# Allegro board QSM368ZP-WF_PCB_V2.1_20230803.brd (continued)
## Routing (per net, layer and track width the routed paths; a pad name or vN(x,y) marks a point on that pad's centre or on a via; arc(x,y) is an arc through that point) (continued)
GND_FIELD SIGNAL: length 54.9
  TOP w0.5: J0901.15 116.65,9.92 116.65,15.43 114.78,17.3 D0901.2 113.84,18.19 R0946.1 113.88,19.62 113.42,20.07 C0920.1 C0909.1 ; v1(103.62,12.22) 106.09,14.69 D0903.2 107.53,17.43 C0901.1
  INNER LAYER 3 w0.5: J0901.15 116.75,8.68 116.75,4.28 115.25,2.77 108.35,2.77 101.78,9.35 J0901.16 102.69,12.22 v1(103.62,12.22)
VBATT: length 144.6
  TOP w0.1: v1(25.38,83.1) 26.85,81.62 v1(28.18,81.62)
  TOP w0.25: R0515.2 12.12,92.03 11.88,92.28 11.88,92.3 9.9,94.28 9.9,97.75 11.15,99 13.4,99 14.3,98.1 C0530.1
  TOP w0.3: C0530.1 R0504.2 U0502.1 ; v1(81.28,68.03) 83.08,69.83 84.33,69.83 90.62,76.12 90.62,83.85 89.67,84.8 89.67,85.65 v1(89.58,85.75)
  TOP w0.5: R0515.2 13.53,90.05 13.17,89.7 13.17,85.97 13.67,85.47 R0120.2
  TOP w1: R0120.2 18.3,85.47
  TOP w1.82: J0102.1 22,83.38 19.9,85.47 18.3,85.47
  TOP w1.9: 74.7,85.03 73.27,83.59 69.26,83.59
  TOP w3: 60.3,79.35 63.73,79.35 67.41,83.04
  BOTTOM w0.1: 32.33,77.35 C0119.2 ; 33.45,78.85 33.23,79.08 33.23,79.7 L0103.2 ; 22.3,82.97 J0102.1 ; v1(28.18,81.62) 28.2,81.62 30.98,78.85 ; v1(25.38,83.1) 25.38,83.15 R0115.1 ; C0502.2 R0510.2
  BOTTOM w0.2: R1211.1 v1(81.28,68.03)
  BOTTOM w0.3: 87.84,86.34 88.43,85.75 v1(89.58,85.75)
  BOTTOM w0.4: U0202.1 C0213.2 82.41,87.16 82.41,85.8 ; v1(74.83,85.03) C0204.2 U0205.1 ; v1(67.99,83.62) 67.26,84.35 C0502.2 U0501.1 ; U0203.1 C0215.2 78.47,85.8
  BOTTOM w0.7: 56.08,76.67 56.08,75.28 58.1,73.25 59.38,73.25 60.7,71.92 C0512.2 ; 56.08,76.67 58.18,78.78 ; 56.08,76.67 56.08,78.72 56.12,78.78 ; v1(58.92,78.25) 59.12,78.05
  BOTTOM w0.8: 89.15,89.26 89.15,87.65 87.3,85.8 82.99,85.8
  BOTTOM w1.1: 78.47,85.8 82.99,85.8
  BOTTOM w1.5: 78.47,85.8 77.7,85.03 v1(75.42,85.03) v1(74.83,85.03)
  BOTTOM w2: 22.3,82.33 23.4,81.22
  BOTTOM w3: 58.18,78.78 51.8,78.78
  BOTTOM w3.2: 23.4,80.83 25.38,78.85 33.45,78.85
  vias: v1(35.77,80.3) v1(35.77,79.8) v1(35.77,79.3) v1(36.27,80.3) v1(36.27,79.8) v1(36.27,79.3) v1(50.7,79.9) v1(50.7,79.4) v1(50.7,78.9) v1(51.2,79.92) v1(51.2,79.4) v1(51.2,78.9) v1(58.92,79.25) v1(58.92,78.75) v1(59.42,79.28) v1(59.42,78.78) v1(59.42,78.28) v1(75.1,84.53)
VBATT_M: length 58.5
  TOP w0.2: TP1301.1 23,44.45 23,37.27 19.05,33.33 19.05,28.25 26.43,20.88 34.22,20.88 37.5,24.15 37.5,25.25 38.02,25.77 R1455.2
  TOP w0.5: U1301.161 23.07,50.67 21.38,48.98 TP1302.1 TP1301.1
  TOP w1: R0120.1 18.3,82.67
  TOP w1.82: 18.3,82.67 J0102.2
  BOTTOM w2: J0102.2 19.45,80.05
  vias: v1(23.73,53.17) v1(24.27,53.17) v1(24.8,53.98) v1(24.82,53.17) v1(24.82,52.58) v1(25.43,53.98) v1(25.38,52.38)
VBUS_USB_HOST1: length 15.8
  TOP w0.4: J0301.10 46.04,14.21 44.17,12.35 42.23,12.35 41.38,13.2 v1(41.38,13.28)
  TOP w0.8: 40.7,16.7 41.65,17.65 41.65,19.38
  INNER LAYER 2 w0.4: v1(41.38,13.28) 42.38,12.28 44.1,12.28 46.04,14.21 J0301.10
  vias: v1(41.42,19.6) v1(41.92,19.6)
VBUS_USB_HOST2: length 9
  TOP w0.9: 82.71,18.41 83.99,18.41 86.22,16.18 86.22,15.32
  BOTTOM w1: 79.45,24.4 79.45,20.9 79.55,21 v1(79.62,21)
  vias: v1(79.1,21)
VBUS_USB_HOST3: length 19
  TOP w0.9: 86.22,12.71 86.06,12.88 82.03,12.88 81.12,13.78 ; v1(73.17,23.8) 75.1,23.8 78.03,20.88 78.03,17.9 81.14,14.79
  vias: v1(72.67,23.8)
VCC3V3_PMU: length 99.3
  TOP w0.2: v1(29.88,58.7) 29.65,58.92 U1301.129 ; R0809.1 66.65,18.85 v1(66.08,18.85)
  BOTTOM w0.2: v1(29.88,58.7) 29.7,58.52 29.7,51.3 26.9,48.5 24.4,48.5 22.73,46.83 22.73,45.33 25.65,42.4 25.65,32.45 24.7,31.5 24.7,24.82 25.24,24.29 25.24,21.6 29.8,17.04 29.8,15.12 32.3,12.62 35.75,12.62 37.4,14.28 37.4,15.22 38.98,16.8 40.55,16.8 43.05,19.3 43.05,21.73 45.08,23.75 54.17,23.75 59.1,18.82 66.05,18.82 v1(66.08,18.85)
VCC3V3_SD: length 29.8
  TOP w0.8: R0813.1 73.12,20.45 70.08,23.5 62.45,23.5 55.23,30.73 50.95,30.73 50.31,31.36
  INNER LAYER 2 w0.8: 50.2,32 50.2,33.7
  vias: v1(50,31.8) v1(50.2,33.92) v1(50.5,31.8) v1(50.7,33.92)
VCC5V0_SYS: length 0.6
  INNER LAYER 2 w0.1: v1(24.88,45.67) 24.9,45.65 25.05,45.65 v1(25.32,45.92)
  vias: v1(24.88,46.2)
VCC5V0_USB: length 96.5
  TOP w1.5: v1(63.48,26.62) v1(64.03,26.62) 64.28,26.38 70.72,26.38 70.97,26.62
  INNER LAYER 2 w0.1: v1(37.77,52.3) 37.02,52.3 31.38,46.65 v1(31.38,45.02)
  BOTTOM w0.1: R0622.1 R0623.1 ; R0305.1 R0308.1 ; R0606.1 v1(37.77,52.3)
  BOTTOM w0.2: R0623.1 35.15,22.35 ; R0614.1 R0612.1 68.42,26.05 69.04,26.67 70.84,26.67 71.53,27.35 71.62,27.35 v1(71.66,27.31) ; R0602.1 73.38,26.1 R0666.1 ; R0602.1 R0604.1 ; R0602.1 75.62,26.1 75.97,26.45 78.17,26.45 78.95,27.23 ; 34.42,17.85 34.2,17.62 31.12,17.62 R0308.1
  BOTTOM w1: 41.67,24.07 41.67,25.07 40.88,25.88 38.98,25.88 37.25,27.6 36.48,27.6 ; 35.15,18.02 35.15,27.05
  BOTTOM w1.5: 36.62,29.43 39.42,26.62 v1(62.95,26.62) v1(63.48,26.62)
  BOTTOM w3: 36.2,30.15 36.2,33.17 32.15,37.23 32.15,41.47
  vias: v1(71.22,27) v1(71.78,26.8)
VCC_1V8: length 105.5
  TOP w0.2: v1(6.65,29.98) 6.22,30.4 6.22,39.08 1.65,43.65 1.65,49.1 5.72,53.17 5.72,71.2 v1(5.58,71.35) ; U1301.139 30.2,56.83 v1(30.2,57) ; v1(20.18,29.2) 20.68,28.7 20.68,27.7 22.58,25.79 v1(25.32,25.79)
  INNER LAYER 3 w0.2: v1(30.2,57) 29.95,56.75 29.95,51.17 26.95,48.17 24.52,48.17 23.07,46.73 23.07,45.35 25.95,42.48 25.95,32.33 25.05,31.43 25.05,26.07 v1(25.32,25.79) ; v1(20.18,29.2) 20.02,29.35 7.38,29.35 6.75,29.98 v1(6.65,29.98)
  BOTTOM w0.2: R1022.2 v1(5.58,71.35)
VCC_PMUIO2: length 128.2
  TOP w0.2: v1(53.75,92.35) 53.77,92.33 53.77,90.97 52.77,89.97 45.08,89.97 44.73,89.62 43.25,89.62 42.12,90.75 39.45,90.75 38.98,91.22 R0508.2 R0517.2 ; U1301.355 v1(59.8,57.08)
  TOP w0.25: v1(76.4,71.55) 77.8,72.95 83.08,72.95 83.42,73.3 v1(84.15,73.3) 85.37,73.3 88.97,76.9 88.97,83.25 v1(89.2,83.47)
  INNER LAYER 3 w0.2: v1(76.4,71.55) 75.53,71.55 74.25,70.28 69.15,70.28 64.72,65.85 60.85,65.85 59.8,64.8 v1(59.8,57.08) ; v1(89.2,83.47) 89,83.67 80.04,83.67 78.29,81.92 74.07,81.92 69.92,86.07 69.92,94.9 67.78,97.05 55.08,97.05 54.17,96.15 54.17,93.92 54.6,93.5 54.6,93.03 54.4,92.83 53.95,92.83 53.75,92.62 v1(53.75,92.35)
  BOTTOM w0.1: R1204.2 85,72.1 84.15,72.95 v1(84.15,73.3)
  BOTTOM w0.2: R1205.1 84.95,74.47 84.15,73.67 v1(84.15,73.3)
VCCA1V8_IMAGE: length 117.6
  TOP w0.3: U1301.124 30.45,61.08 v1(30.51,61.14)
  INNER LAYER 2 w0.2: v1(43.65,41.02) 43.15,41.52 28.55,41.52 27.48,42.6 v1(26.6,42.6)
  INNER LAYER 3 w0.2: v1(26.6,42.6) 23.62,45.58 23.62,46.53 24.75,47.65 27.2,47.65 30.48,50.93 30.48,56.27 31,56.8 31,60.65 v1(30.51,61.14)
  INNER LAYER 3 w0.3: v1(30.51,61.14) 30.95,61.58 30.95,70 33.08,72.12 35.25,72.12 35.85,72.72 36.73,72.72 38.88,74.88 38.88,87.08 36.4,89.55 36.4,90.55 35.75,91.2 33.95,91.2 32.4,89.65 20.45,89.65 19.05,91.05 17.77,91.05 16.2,92.62 16.2,95.05 v1(18.07,96.92)
  BOTTOM w0.25: 43.68,39.83 43.68,41 v1(43.65,41.02) ; 43.68,39.83 44.25,39.83 44.48,39.6 R1468.2 ; 43.68,39.83 R1466.2
  BOTTOM w0.3: R0511.1 19.68,98.53 v1(18.07,96.92)
VCCIO4: length 159.8
  TOP w0.2: v1(37.35,90.45) 37.35,91.08 37.55,91.28 37.55,96.25 36.5,97.3 36.5,98.08 v1(36,98.58) ; U1301.180 v1(25.95,44.27)
  TOP w0.3: v1(91.15,86.1) 91.15,84.58 91.62,84.1 91.62,75.78 88.72,72.88 v1(88.72,71.38)
  INNER LAYER 3 w0.2: v1(36,98.58) 36.7,97.88 42.02,97.88 42.33,97.58 44.92,97.58 45.38,97.12 47.7,97.12 48.15,97.58 52.27,97.58 v1(52.6,97.9) 53.2,97.9 53.67,98.38 68.35,98.38 71.47,95.25 71.47,90.08 72.12,89.42 82.95,89.42 85.67,86.7 89.67,86.7 89.97,86.4 90.85,86.4 v1(91.15,86.1) ; v1(37.35,90.45) 37.35,89.1 39.25,87.2 39.25,74.75 36.28,71.78 33.22,71.78 31.3,69.85 31.3,56.67 30.77,56.15 30.77,50.8 27.3,47.33 24.85,47.33 23.93,46.4 23.93,45.7 25.35,44.27 v1(25.95,44.27)
  BOTTOM w0.2: R1203.2 R1206.2 v1(88.72,71.38) 88.72,72.4 86.65,74.47 R1202.1
  BOTTOM w0.25: v1(52.6,97.9) 52.6,97.47 50.73,95.6 U0407.1 50.82,95.03 U0410.1
VCCIO5: length 202.7
  TOP w0.2: U1301.371 v1(67.5,60.27) ; R1017.2 v1(19.18,15.93)
  TOP w0.25: v1(92.45,40.02) 92.3,40.02 90.22,37.95 v1(85.47,37.95)
  INNER LAYER 2 w0.2: v1(90.03,32.83) 90.05,32.8 90.05,27.18 v1(90.03,27.15)
  INNER LAYER 3 w0.2: 99.25,53.5 98.58,54.17 89.78,54.17 89.5,54.45 v1(87.72,54.45) 87.72,43.83 91.53,40.02 v1(92.45,40.02) ; v1(19.18,15.93) 19.82,15.93 22.23,13.53 26.12,13.53 28.8,10.85 28.8,10.1 33.02,5.88 40.75,5.88 43,3.62 56.83,3.62 59.1,5.9 78.72,5.9 80.7,7.88 80.7,17.62 90.03,26.95 v1(90.03,27.15) ; v1(67.5,60.27) 67.67,60.27 69.35,58.6 74.6,58.6 77.08,56.12 77.08,46.35 v1(85.47,37.95) 89.55,33.88 89.55,33.3 v1(90.03,32.83)
  INNER LAYER 3 w0.25: v1(104.22,53.08) 103.83,53.48 99.28,53.48 99.25,53.5
  BOTTOM w0.075: U1102.B2 103.5,56.85 103.72,56.62 104.62,56.62
  BOTTOM w0.1: 104.62,56.62 104.67,56.62 105,56.3 R1107.2
  BOTTOM w0.2: R0705.2 93.2,63.9 92.55,63.25 92.55,60.92 89.72,58.1 U0702.1 87.8,58.1 87.58,57.88 87.58,56.95 87.72,56.8 v1(87.72,54.45)
  BOTTOM w0.25: v1(104.22,53.08) C1103.2 C1108.1 R1107.2
VCCIO6: length 62
  TOP w0.2: v1(71.83,34.62) 70.92,34.62 69.28,36.27 U1301.302 ; v1(74.97,46.33) 75.15,46.5 87.7,46.5 90.75,49.55 90.75,51.98 93.03,54.25 98.95,54.25 99.62,54.92 106.35,54.92 107.28,54 107.58,54 108.05,53.52 v1(108.25,53.52)
  INNER LAYER 3 w0.2: v1(71.83,34.62) 73.47,36.27 74.6,36.27 76.6,38.27 76.6,42.6 74.97,44.23 v1(74.97,46.33)
  BOTTOM w0.2: v1(108.25,53.52) 109.72,53.52 111.25,52 R0941.1
VCCIO7: length 176.3
  TOP w0.2: v1(89.45,29.43) 89.45,34.95 v1(91.38,36.88) ; v1(79,70.1) 78.22,70.88 70.38,70.88 69.38,69.88 U1301.389
  INNER LAYER 3 w0.2: v1(91.38,36.88) 91.2,36.88 80.08,48 80.08,57.52 79.22,58.38 79.22,69.88 v1(79,70.1) ; v1(89.45,29.43) 89.45,26.8 80.4,17.75 80.4,8.03 78.58,6.2 58.98,6.2 56.7,3.92 43.12,3.92 40.88,6.17 33.15,6.17 29.1,10.22 29.1,10.97 26.23,13.85 22.32,13.85 19.77,16.4 v1(19.77,18.15)
  BOTTOM w0.2: 12.65,21.98 14.53,21.98 R0428.2 14.56,22.01 18.42,22.01 19.73,20.7 19.73,18.2 v1(19.77,18.15) ; 12.65,21.98 12.65,20.13 D0404.1 ; 12.65,21.98 9.12,21.98 ; 9.12,21.98 9.22,21.88 U0413.1 ; 9.12,21.98 6.7,21.98 ; 6.7,21.98 6.25,21.98 5.7,21.42 U0405.1 ; 6.7,21.98 R0417.2
VCCIO_ACODEC: length 188.6
  TOP w0.2: v1(47.23,88.88) 33.92,88.88 33.55,89.25 20.45,89.25 v1(20.12,88.92) 19.25,88.05 B1002.1 ; v1(5.85,85.95) 5.72,85.83 5.72,72.15 5.1,71.53 5.1,71.17 5.42,70.85 5.42,53.33 1.35,49.25 1.35,43.5 5.92,38.92 5.92,30.27 6.15,30.05 6.15,29.25 6.72,28.68 v1(6.72,27.88) ; v1(57.98,21.12) 57.98,21.3 52.9,26.38 40.25,26.38 34.45,20.57 26.27,20.57 v1(18.5,28.35)
  TOP w0.3: v1(62.91,25.19) 62.34,25.19 56.55,30.98 U1301.282
  INNER LAYER 3 w0.2: v1(5.85,85.95) 7.15,85.95 7.78,86.58 11.72,86.58 13.85,88.7 19.9,88.7 v1(20.12,88.92) ; v1(62.91,25.19) 58.72,20.99 58.11,20.99 v1(57.98,21.12) ; v1(6.72,27.88) 6.97,27.88 7.7,28.6 18.25,28.6 v1(18.5,28.35)
  BOTTOM w0.2: R0403.2 46.58,89.5 46.58,89.09 47.01,89.09 v1(47.23,88.88)
VDD_2V8: length 6.6
  TOP w0.23: J0501.14 26.27,98.3
  TOP w0.3: 26.27,98.3 26.27,98.42 25.98,98.72 23.77,98.72 TP0504.1 23.57,98.53 C0507.1 C0508.1 22.55,98.35 B0503.2
VDD_AF0_2V8: length 18.6
  TOP w0.2: J0201.3 v1(96.85,98.5)
  BOTTOM w0.2: R0229.2 82.39,95.37 82.39,95.77 83.08,96.45 83.08,97.4 84.12,98.45 93.47,98.45 93.75,98.17 94.22,98.17 94.55,98.5 C0203.1 v1(96.85,98.5)
VDD_AF1_2V8: length 5.9
  TOP w0.2: v1(85.56,96.92) 85.82,96.92 86.17,97.28 J0202.3
  BOTTOM w0.2: v1(85.56,96.92) 85.56,96.23 85.3,95.97 C0206.1 84.85,95.45 84.05,94.65 R0209.2
4G_PWREN_H_GPIO0_C6: length 265.2
  TOP w0.1: v1(18.98,25.6) 19.2,25.82 19.2,26.77 17.88,28.1 17.88,30.65 v1(18.35,31.12) ; v1(61.65,61.88) U1301.370 ; v1(77.15,7.12) 77.35,6.92 78.38,6.92 81.17,4.12 97.97,4.12 99.45,2.65 115.38,2.65 118.53,5.79 118.53,16.68 113.7,21.5 113.7,25.3 115.45,27.05 115.45,28.69 118.05,31.29 118.05,48.4 116.97,49.48 116.97,52.23 115.3,53.9 113,53.9 108.77,58.13 100.58,58.13 98.92,59.78 98.92,67.67 98.5,68.1 v1(97.53,68.1)
  INNER LAYER 3 w0.1: v1(97.53,68.1) 97.03,68.6 90.35,68.6 88.8,67.05 87.45,67.05 87.2,66.8 80.78,66.8 80.45,67.12 80.45,70.12 80,70.58 75.88,70.58 74.95,69.65 69.28,69.65 64.35,64.72 63.98,64.72 61.65,62.4 v1(61.65,61.88) ; v1(77.15,7.12) 76.88,6.85 58.52,6.85 56.3,4.62 43.4,4.62 41.17,6.85 33.45,6.85 29.77,10.53 29.77,11.28 26.52,14.53 22.65,14.53 21.1,16.07 21.1,23.48 v1(18.98,25.6) ; v1(18.35,31.12) 18.15,30.93 8.62,30.93 7.08,32.48 7.08,34.5 7.35,34.77 v1(7.47,34.77)
  BOTTOM w0.1: D0501.1 v1(7.47,34.77)
4G_USIM_CLK: length 36
  TOP w0.1: J0701.12 86.88,34.83 86.53,34.48 86.53,30.6 86.58,30.55 v1(86.58,30.35)
  INNER LAYER 3 w0.1: v1(66.75,22.62) 66.97,22.4 70.58,22.4 71.65,21.32 74.07,21.32 74.79,22.04 76.46,22.04 78.6,19.9 79.75,19.9 80.85,21 80.85,26.4 84.35,29.9 86.22,29.9 86.58,30.25 v1(86.58,30.35)
  BOTTOM w0.1: R0810.1 67.88,22.62 v1(66.75,22.62)
4G_USIM_DATA: length 27.1
  TOP w0.1: v1(85.97,30.35) 86.28,30.65 86.28,35.55 J0701.10
  INNER LAYER 3 w0.1: v1(85.97,30.35) 85.8,30.18 84.33,30.18 80.6,26.45 80.6,21.05 79.72,20.18 78.66,20.18 76.56,22.27 74.69,22.27 74.33,21.92 73.88,21.92 v1(73.86,21.94)
  BOTTOM w0.1: R0808.1 73.38,22.43 v1(73.86,21.94)
4G_USIM_DET: length 76
  TOP w0.1: J0701.44 v1(102.88,30.55) ; v1(84.75,7.72) 84.55,7.53 82.6,7.53 77.62,12.5 v1(77.62,16.6)
  INNER LAYER 3 w0.1: v1(77.62,16.6) 77.17,16.6 76.08,15.5 71.03,15.5 70.6,15.93 70.6,18.73 71.08,19.2 v1(71.08,19.52) ; v1(84.75,7.72) 84.75,19.43 89.6,24.27 91.47,24.27 92.1,24.9 92.1,26.1 97.2,31.2 102.22,31.2 v1(102.88,30.55)
  BOTTOM w0.1: J0802.CD 77.75,18.39 76.5,19.65 75.58,19.65 75.08,20.15 R0866.2 70.75,20.15 70.53,20.38 D0803.6 70.33,19.7 70.5,19.52 v1(71.08,19.52)
4G_USIM_RTS: length 37.5
  TOP w0.1: J0701.14 87.67,30.73 v1(87.17,30.23)
  INNER LAYER 3 w0.1: v1(87.17,30.23) 87.05,30.23 86.47,29.65 84.42,29.65 81.05,26.27 81.05,20.88 79.83,19.65 78.55,19.65 76.38,21.82 74.88,21.82 74.12,21.07 71.55,21.07 70.5,22.12 66.3,22.12 v1(65.92,22.5)
  BOTTOM w0.1: v1(65.92,22.5) 65.67,22.25 R0803.1
4G_USIM_VDD: length 55.1
  TOP w0.3: v1(72.22,22.6) 72.4,22.77 74.17,22.77 74.65,22.3 75.25,22.3 76.92,20.62 76.92,14.8 v1(76.78,14.65)
  TOP w0.5: J0701.8 85.28,34.52 84.58,33.83 84.58,32.12 81.38,28.93 81.38,26.1 v1(81.92,25.55)
  INNER LAYER 3 w0.5: v1(68.1,19.82) 68.1,19.7 68.58,19.23 68.58,15.45 69.35,14.68 76.75,14.68 v1(76.78,14.65) 77.42,14.65 79.1,16.32 79.1,17.7 81.92,20.52 v1(81.92,25.55)
  BOTTOM w0.3: D0803.1 68.92,20.05 68.67,19.8 68.12,19.8 v1(68.1,19.82) 68.08,19.8 67.45,19.8 C0801.2 67.42,18.93 67.59,18.75 J0802.C1 ; v1(72.22,22.6) 72.15,22.52 72.15,21.9 R0804.2
50OHM_ANTWIFI0: length 2.9
  TOP w0.5: R1407.2 C1402.2 U1401.3
50OHM_GMAC1_MCLKINOUT_M1: length 76.4
  TOP w0.125: v1(113.03,46.05) 113.17,46.2 113.17,49.65 108.25,54.58 107.5,54.58 106.6,55.48 99.35,55.48 98.67,54.8 92.78,54.8 90.2,52.23 90.2,49.8 87.45,47.05 72.97,47.05 71.7,45.77 v1(70.97,45.77) ; U1301.278 v1(56.48,36.67)
  INNER LAYER 3 w0.109: v1(56.48,36.67) 56.65,36.5 59.05,36.5 59.62,37.08 59.62,38.2 61.18,39.75 62.58,39.75 68.6,45.77 v1(70.97,45.77)
  BOTTOM w0.125: v1(113.03,46.05) 111.97,46.05 111.4,45.48 R0926.1 R0934.2
50OHM_GMAC1_RXCLK_M1: length 63.3
  TOP w0.125: U1301.304 70.33,37.88 71.65,36.55 74.65,36.55 80.58,42.48 88.45,42.48 92.53,46.55 92.53,47.27 92.7,47.45 93.05,47.45 93.17,47.33 93.17,47.02 93.3,46.9 93.55,46.9 93.67,47.02 93.67,47.33 93.8,47.45 94.05,47.45 94.17,47.33 94.17,47.02 94.3,46.9 94.55,46.9 94.67,47.02 94.67,47.33 94.8,47.45 95.05,47.45 95.17,47.33 95.17,47.02 95.3,46.9 95.5,46.9 95.62,47.02 95.62,47.33 95.75,47.45 96,47.45 96.12,47.33 96.12,47.02 96.25,46.9 96.53,46.9 96.65,47.02 96.65,47.96 96.78,48.09 97.03,48.09 97.15,47.96 97.15,47.65 97.28,47.52 97.53,47.52 97.65,47.65 97.65,47.96 97.78,48.09 98.03,48.09 98.15,47.96 98.15,47.65 98.28,47.52 98.53,47.52 98.65,47.65 98.65,47.96 98.78,48.09 99.03,48.09 99.15,47.96 99.15,47.65 99.28,47.52 99.53,47.52 99.65,47.65 99.65,48.46 99.53,48.59 96.78,48.59 96.65,48.71 96.65,50.8 96.78,50.92 97.12,50.92 97.25,50.8 97.25,50.17 97.38,50.05 97.71,50.05 97.83,50.17 97.83,50.8 97.96,50.92 98.21,50.92 98.33,50.8 98.33,50.17 98.46,50.05 98.71,50.05 98.83,50.17 98.83,50.8 98.96,50.92 99.21,50.92 99.33,50.8 99.33,50.17 99.46,50.05 99.71,50.05 99.83,50.17 99.83,50.8 99.96,50.92 100.21,50.92 100.33,50.8 100.33,50.17 100.46,50.05 100.71,50.05 100.83,50.17 100.83,50.8 100.96,50.92 101.21,50.92 101.33,50.8 101.33,50.17 101.46,50.05 101.75,50.05 102,50.3 v1(102,52.1)
  BOTTOM w0.125: v1(102,52.1) R0920.2
50OHM_GMAC1_RXD0_M1: length 61.4
  TOP w0.125: v1(98.6,52.1) 99.05,52.55 99.6,52.55 100.4,53.35 102.83,53.35 103.42,52.75 103.42,49.12 102.75,48.45 102.75,48.2 102.95,48 102.95,47.77 101.6,46.42 100.72,46.42 100.01,45.71 100.01,44.61 98.47,43.08 96.6,43.08 95.7,43.98 94.83,43.98 94.28,43.42 93.8,43.42 89.75,39.38 81.83,39.38 75,32.55 70.17,32.55 69.44,33.29 67.69,33.29 65.12,35.85 63.88,35.85 63.65,35.62 63.65,35.05 63.38,34.77 U1301.296
  BOTTOM w0.125: v1(98.6,52.1) R0906.2
50OHM_GMAC1_RXD1_M1: length 61.4
  TOP w0.125: U1301.294 65.2,36.67 67.92,33.95 69.75,33.95 70.5,33.2 74.75,33.2 81.58,40.02 89.49,40.02 93.54,44.08 94.03,44.08 94.67,44.73 95.92,44.73 96.92,43.73 98.17,43.73 99.33,44.88 99.33,45.98 102.79,49.44 102.79,52.46 102.54,52.71 100.66,52.71 99.62,51.67 96.45,51.67 96.05,52.08 v1(96.05,52.1)
  BOTTOM w0.125: v1(96.05,52.1) R0955.2
50OHM_GMAC1_RXD2_M1: length 55.9
  TOP w0.125: v1(95.2,52.1) 94.11,52.1 93.98,51.98 93.98,51.76 94.11,51.63 95.86,51.63 95.98,51.51 95.98,49.83 95.86,49.7 95.61,49.7 95.48,49.83 95.48,51.01 95.36,51.13 95.11,51.13 94.98,51.01 94.98,49.83 94.86,49.7 94.61,49.7 94.48,49.83 94.48,51.01 94.36,51.13 94.11,51.13 93.98,51.01 93.98,49.7 93.86,49.58 93.61,49.58 93.48,49.7 93.48,51.8 93.36,51.92 93.11,51.92 92.98,51.8 92.98,49.7 92.86,49.58 92.61,49.58 92.48,49.7 92.48,51.8 92.36,51.92 92.1,51.92 91.58,51.4 91.58,46.9 88.15,43.48 75.1,43.48 74.67,43.9 71.55,43.9 69.7,42.05 69.7,41.85 69.22,41.38 69.22,40.4 69.1,40.27 U1301.308
  BOTTOM w0.125: v1(95.2,52.1) R0903.2
50OHM_GMAC1_RXD3_M1: length 51.3
  TOP w0.125: v1(92.03,51.23) 91.9,51.1 91.9,48.71 92.03,48.59 92.96,48.59 93.08,48.71 93.08,49.12 93.21,49.25 93.46,49.25 93.58,49.12 93.58,48.71 93.71,48.59 94.59,48.59 94.72,48.71 94.72,49.2 94.84,49.33 95.09,49.33 95.22,49.2 95.22,48.71 95.34,48.59 95.85,48.59 95.97,48.46 95.97,48.21 95.85,48.09 92.03,48.09 91.9,47.96 91.9,46.77 88.25,43.12 79.82,43.12 79.44,42.75 79.44,42.2 79.32,42.08 79.07,42.08 78.94,42.2 78.94,42.75 78.82,42.88 78.57,42.88 78.44,42.75 78.44,41.2 78.32,41.08 78.07,41.08 77.94,41.2 77.94,42.75 77.82,42.88 77.57,42.88 77.44,42.75 77.44,41.15 77.32,41.02 77.07,41.02 76.94,41.15 76.94,42.75 76.59,43.1 75.03,43.1 74.55,43.58 71.67,43.58 70.03,41.92 70.03,41.73 69.55,41.25 69.55,40.08 68.95,39.48 U1301.307
  BOTTOM w0.125: R0932.2 92.28,51.48 v1(92.03,51.23)
50OHM_GMAC1_RXDV_CRS_M1: length 62.2
  TOP w0.125: v1(99.45,52.1) 99.6,52.1 100.53,53.03 102.69,53.03 103.11,52.62 103.11,49.28 102.2,48.38 102.2,48.2 102.44,47.97 102.44,47.79 102.26,47.61 102.09,47.61 101.85,47.85 101.67,47.85 101.5,47.67 101.5,47.49 101.73,47.26 101.73,47.08 101.56,46.91 101.38,46.91 101.14,47.14 100.97,47.14 99.65,45.83 99.65,44.75 98.3,43.4 96.75,43.4 95.8,44.35 94.75,44.35 94.15,43.75 93.67,43.75 89.62,39.7 81.7,39.7 74.88,32.88 70.3,32.88 69.58,33.6 67.83,33.6 65.25,36.17 63.75,36.17 63.15,35.58 61.6,35.58 61.35,35.33 U1301.293
  BOTTOM w0.125: v1(99.45,52.1) R0945.2
50OHM_GMAC1_TXCLK: length 42.4
  TOP w0.125: v1(98.28,45.33) 97.92,45.67 93.38,45.67 88.92,41.23 81.08,41.23 75.17,35.33 74.36,35.33 74.24,35.2 74.24,34.67 74.11,34.55 73.86,34.55 73.74,34.67 73.74,35.2 73.61,35.33 71.15,35.33 69.58,36.9 67.6,36.9 67.22,37.27 67.22,37.6 67.1,37.73 65.45,37.73 64.55,38.62 U1301.306
  BOTTOM w0.125: v1(98.28,45.33) R1307.2
50OHM_GMAC1_TXCLK_M1: length 2.5
  BOTTOM w0.125: U0902.20 R1307.1
50OHM_GMAC1_TXD0: length 41.8
  TOP w0.125: U1301.305 66.45,38.27 66.67,38.05 67.25,38.05 67.55,37.75 67.55,37.4 67.72,37.23 70.12,37.23 71.4,35.95 74.95,35.95 80.85,41.85 88.7,41.85 93.15,46.3 98.4,46.3 98.97,45.73 98.97,45 98.22,44.25 v1(98.08,44.25)
  BOTTOM w0.125: v1(98.08,44.25) 98.08,44.05 98.5,43.62 R1302.2
50OHM_GMAC1_TXD0_M1: length 2.9
  BOTTOM w0.125: R1302.1 100.72,43.62 101.62,44.52 U0902.18
50OHM_GMAC1_TXD1: length 41.2
  TOP w0.125: U1301.303 66.45,36.55 67.55,35.45 69.2,35.45 70.75,33.9 74.6,33.9 81.33,40.62 89.2,40.62 93.65,45.08 96.25,45.08 v1(97.12,44.2)
  BOTTOM w0.125: R1303.2 98.55,42.77 98.02,43.31 97.84,43.31 97.38,42.85 97.2,42.85 97.03,43.02 97.03,43.2 97.49,43.66 97.49,43.84 v1(97.12,44.2)
50OHM_GMAC1_TXD1_M1: length 3.1
  BOTTOM w0.125: U0902.17 101.67,44.12 100.33,42.77 R1303.1
50OHM_GMAC1_TXD2: length 42.8
  TOP w0.125: v1(90.25,47.42) 90.12,47.3 90.12,46.52 87.74,44.14 75.41,44.14 74.97,44.58 71.1,44.58 69.05,42.52 69.05,42.15 68.85,41.95 67.1,41.95 67.03,41.88 U1301.312
  BOTTOM w0.125: v1(90.25,47.42) 90.88,47.42 92.12,46.17 94.08,46.17 94.9,45.35 95.96,45.35 96.09,45.23 96.09,44.9 95.96,44.77 95.03,44.77 94.9,44.65 94.9,44.35 95.03,44.23 95.47,44.23 95.6,44.1 95.6,43.85 95.47,43.73 95.03,43.73 94.9,43.6 94.9,42.82 95.8,41.92 R1304.2
50OHM_GMAC1_TXD2_M1: length 3.3
  BOTTOM w0.125: R1304.1 99.92,41.92 101.72,43.73 U0902.16
50OHM_GMAC1_TXD3: length 43.6
  TOP w0.125: U1301.310 62.85,41.67 65.35,41.67 65.75,41.27 67.22,41.27 67.58,41.62 68.97,41.62 69.38,42.02 69.38,42.38 71.25,44.25 74.85,44.25 75.28,43.83 87.92,43.83 90.65,46.55 v1(90.65,46.98)
  BOTTOM w0.125: v1(90.65,46.98) 90.88,46.98 92,45.85 93.95,45.85 94.58,45.23 94.58,42.7 95.7,41.58 97.96,41.58 98.46,41.08 R1305.2
50OHM_GMAC1_TXD3_M1: length 3.8
  BOTTOM w0.125: U0902.15 101.78,43.33 100.45,42 100.45,41.42 100.1,41.08 R1305.1
50OHM_GMAC1_TXEN: length 42
  TOP w0.125: U1301.298 65.28,34.77 66.28,33.77 66.28,32.08 66.55,31.8 75.1,31.8 82.06,38.76 89.99,38.76 94.03,42.8 95.12,42.8 v1(95.42,43.1)
  BOTTOM w0.125: R1306.2 98.7,44.67 96.92,44.67 95.42,43.17 v1(95.42,43.1)
50OHM_GMAC1_TXEN_M1: length 2.8
  BOTTOM w0.125: R1306.1 99.9,44.38 100.92,44.38 101.47,44.92 U0902.19
50OHM_RXC/PHYAD1_A: length 7.9
  BOTTOM w0.125: 102,50.58 101.15,50.58 101.2,50.52 R0917.1 101.2,49.67 101.62,49.25 102.8,49.25 105.28,46.77 105.28,45.88
50OHM_RXCTL/PHYAD2_A: length 8.7
  BOTTOM w0.125: U0902.26 104.88,46.73 102.67,48.92 100.55,48.92 100.35,49.12 R0940.1 100.35,49.91 100.3,49.96 100.3,50.58 99.45,50.58
50OHM_RXD0/RXDLY_A: length 9.9
  BOTTOM w0.125: 97.75,50.58 98.6,50.58 R0952.1 98.6,49.35 99.35,48.6 102.55,48.6 104.47,46.67 U0902.25
50OHM_RXD1/CFG_MODEO_A: length 11.2
  BOTTOM w0.125: 96.05,50.58 96.9,50.58 96.9,49.96 96.85,49.91 R0944.1 96.85,49.35 97.92,48.27 102.42,48.27 104.08,46.62 U0902.24
50OHM_RXD2/CFG_MODE1_A: length 15.3
  BOTTOM w0.125: 94.35,50.58 95.2,50.58 95.2,50.01 95.1,49.91 R0916.1 95.1,48.3 95.46,47.94 95.64,47.94 95.77,48.07 95.77,48.55 95.89,48.67 96.14,48.67 96.27,48.55 96.27,48.07 96.39,47.94 96.64,47.94 96.77,48.07 96.77,48.45 96.89,48.58 97.14,48.58 97.27,48.45 97.27,48.07 97.39,47.94 102.31,47.94 103.67,46.58 U0902.23
50OHM_RXD3/CFG_MODE2_A: length 19
  BOTTOM w0.125: 103.28,45.88 103.28,46.52 102.17,47.62 98.59,47.62 98.46,47.5 98.46,47.27 98.34,47.15 98.09,47.15 97.96,47.27 97.96,47.5 97.84,47.62 97.59,47.62 97.46,47.5 97.46,47.3 97.34,47.17 97.09,47.17 96.96,47.3 96.96,47.5 96.84,47.62 96.59,47.62 96.46,47.5 96.46,47.27 96.34,47.15 96.09,47.15 95.96,47.27 95.96,47.5 95.84,47.62 95.08,47.62 94.74,47.96 94.56,47.96 94.26,47.66 94.09,47.66 93.91,47.84 93.91,48.02 94.21,48.31 94.21,48.49 94.03,48.67 93.85,48.67 93.17,47.98 92.99,47.98 92.82,48.16 92.82,48.34 93.5,49.02 93.5,49.2 93.35,49.35 R0902.1 93.35,49.99 93.5,50.14 93.5,50.58 92.65,50.58
50OHM_SDMMC0_CLK: length 31.1
  TOP w0.125: R0811.1 68.92,19.98 68.4,20.5 62.17,20.5 54.33,28.35 49.92,28.35 46.95,31.32 U1301.252
50OHM_SDMMC0_CLK1: length 25.9
  TOP w0.125: J0801.P5 67.92,6.21 67.79,6.34 67.22,6.34 67.1,6.46 67.1,6.71 67.22,6.84 67.79,6.84 67.92,6.96 67.92,7.21 67.79,7.34 67.22,7.34 67.1,7.46 67.1,7.71 67.22,7.84 67.79,7.84 67.92,7.96 67.92,8.21 67.79,8.34 67.22,8.34 67.1,8.46 67.1,8.71 67.22,8.84 67.79,8.84 67.92,8.96 67.92,9.21 67.79,9.34 67.22,9.34 67.1,9.46 67.1,9.71 67.22,9.84 67.79,9.84 67.92,9.96 67.92,10.21 67.79,10.34 67.22,10.34 67.1,10.46 67.1,10.71 67.22,10.84 67.79,10.84 67.92,10.96 67.92,11.21 67.79,11.34 67.22,11.34 67.1,11.46 67.1,11.71 67.22,11.84 67.79,11.84 67.92,11.96 67.92,12.21 67.79,12.34 67.22,12.34 67.1,12.46 67.1,12.71 67.22,12.84 67.79,12.84 67.92,12.96 67.92,13.21 67.79,13.34 67.22,13.34 67.1,13.46 67.1,13.71 67.22,13.84 67.79,13.84 67.92,13.96 67.92,14.21 67.79,14.34 67.22,14.34 67.1,14.46 67.1,14.71 67.22,14.84 67.79,14.84 67.92,14.96 67.92,15.94 68.92,16.95 D0801.1 R0811.2
50OHM_SDMMC0_CMD: length 38.6
  TOP w0.125: R0805.1 73.03,19.25 70.53,21.75 62.67,21.75 54.75,29.68 50.38,29.68 48.55,31.5 48.55,32.08 48.62,32.15 48.62,33.6 48.61,33.61 49.27,34.27 49.27,35.2 48.83,35.65 45.65,35.65 45.35,35.35 U1301.247
50OHM_SDMMC0_CMD1: length 19.6
  TOP w0.125: J0801.P3 70.11,3.94 70.33,3.73 71.28,3.73 71.58,3.42 73.25,3.42 73.78,3.95 73.78,17.7 73.33,18.15 R0805.2
50OHM_SDMMC0_D0: length 25.9
  TOP w0.125: U1301.246 44.55,32.35 49.5,27.4 53.95,27.4 61.77,19.57 64.05,19.57 64.22,19.4 R0801.1
50OHM_SDMMC0_D0_1: length 32.7
  TOP w0.125: R0801.2 64.22,17.77 64.35,17.65 D0804.1 64.35,16.9 63.8,16.35 63.8,15.12 63.67,15 63.02,15 62.9,14.88 62.9,14.62 63.02,14.5 63.67,14.5 63.8,14.38 63.8,14.12 63.67,14 63.02,14 62.9,13.88 62.9,13.62 63.02,13.5 63.67,13.5 63.8,13.38 63.8,13.12 63.67,13 63.02,13 62.9,12.88 62.9,12.62 63.02,12.5 63.67,12.5 63.8,12.38 63.8,12.12 63.67,12 63.02,12 62.9,11.88 62.9,11.62 63.02,11.5 63.67,11.5 63.8,11.38 63.8,11.15 63.67,11.03 63.02,11.03 62.9,10.9 62.9,10.65 63.02,10.53 63.67,10.53 63.8,10.4 63.8,10.15 63.67,10.03 63.02,10.03 62.9,9.9 62.9,9.65 63.02,9.53 63.67,9.53 63.8,9.4 63.8,9.15 63.67,9.03 63.02,9.03 62.9,8.9 62.9,8.65 63.02,8.53 63.67,8.53 63.8,8.4 63.8,8.15 63.67,8.03 63.02,8.03 62.9,7.9 62.9,7.65 63.02,7.53 63.67,7.53 63.8,7.4 63.8,7.15 63.67,7.03 63.02,7.03 62.9,6.9 62.9,6.65 63.02,6.53 63.67,6.53 63.8,6.4 63.8,6.15 63.67,6.03 63.02,6.03 62.9,5.9 62.9,5.65 63.02,5.53 63.67,5.53 63.8,5.4 63.8,3.7 63.92,3.58 65.42,3.58 65.72,3.87 J0801.P7
50OHM_SDMMC0_D1: length 25.9
  TOP w0.125: U1301.251 46.15,32.33 45.95,32.12 45.95,31.4 49.62,27.73 54.08,27.73 61.9,19.9 64.35,19.9 65.08,19.18 R0814.1
50OHM_SDMMC0_D1_1: length 33.5
  TOP w0.125: 64.61,4.71 64.65,4.75 64.65,6.29 64.78,6.42 66.08,6.42 66.2,6.54 66.2,6.77 66.05,6.92 64.78,6.92 64.65,7.04 64.65,7.29 64.78,7.42 66.08,7.42 66.2,7.54 66.2,7.77 66.05,7.92 64.78,7.92 64.65,8.04 64.65,8.29 64.78,8.42 66.08,8.42 66.2,8.54 66.2,8.77 66.05,8.92 64.78,8.92 64.65,9.04 64.65,9.29 64.78,9.42 66.08,9.42 66.2,9.54 66.2,9.77 66.05,9.92 64.78,9.92 64.65,10.04 64.65,10.29 64.78,10.42 66.08,10.42 66.2,10.54 66.2,10.77 66.05,10.92 64.78,10.92 64.65,11.04 64.65,11.29 64.78,11.42 66.08,11.42 66.2,11.54 66.2,11.77 66.05,11.92 64.78,11.92 64.65,12.04 64.65,12.29 64.78,12.42 66.08,12.42 66.2,12.54 66.2,12.77 66.05,12.92 64.78,12.92 64.65,13.04 64.65,14.57 64.4,14.82 64.4,16.2 65.2,17 D0810.1 65.2,17.65 65.08,17.77 R0814.2
50OHM_SDMMC0_D2/ARMJTAG_TCK: length 29.6
  TOP w0.125: U1301.256 47.75,32.33 47.9,32.17 47.9,31.23 50.1,29.02 54.5,29.02 62.42,21.1 69.17,21.1 70.15,20.12 R0802.1
50OHM_SDMMC0_D2/ARMJTAG_TCK1: length 30
  TOP w0.125: J0801.P1 72.31,6.38 71.78,6.92 70.4,6.92 70.12,7.2 70.12,9.65 70,9.78 68.9,9.78 68.78,9.9 68.78,10.15 68.9,10.28 70,10.28 70.12,10.4 70.12,10.65 70,10.78 68.9,10.78 68.78,10.9 68.78,11.15 68.9,11.28 70,11.28 70.12,11.4 70.12,11.65 70,11.78 68.9,11.78 68.78,11.9 68.78,12.15 68.9,12.28 70,12.28 70.12,12.4 70.12,12.65 70,12.78 68.9,12.78 68.78,12.9 68.78,13.15 68.9,13.28 70,13.28 70.12,13.4 70.12,13.66 70,13.79 68.88,13.79 68.75,13.91 68.75,14.16 68.88,14.29 70,14.29 70.12,14.41 70.12,14.66 70,14.79 68.88,14.79 68.75,14.91 68.75,15.16 68.88,15.29 70,15.29 70.12,15.41 70.12,16.38 70.53,16.77 D0802.1 70.53,17.77 R0802.2
50OHM_SDMMC0_D3/ARMJTAG_TMS: length 33
  TOP w0.125: U1301.257 48.55,34.2 48.23,33.88 48.23,33.55 48.3,33.48 48.3,32.27 48.23,32.2 48.23,31.38 50.25,29.35 54.62,29.35 62.55,21.43 70.4,21.43 72.17,19.65 R0806.1
50OHM_SDMMC0_D3/ARMJTAG_TMS1: length 25.1
  TOP w0.125: R0806.2 D0807.1 72.17,16.86 73.45,15.59 73.45,11.99 73.33,11.87 72.25,11.87 72.12,11.74 72.12,11.49 72.25,11.37 73.33,11.37 73.45,11.24 73.45,10.99 73.33,10.87 72.25,10.87 72.12,10.74 72.12,10.49 72.25,10.37 73.33,10.37 73.45,10.24 73.45,9.99 73.33,9.87 72.25,9.87 72.12,9.74 72.12,9.49 72.25,9.37 73.33,9.37 73.45,9.24 73.45,4.1 73.1,3.75 71.72,3.75 71.22,4.26 J0801.P2
50OHM_WIFI_ANT0: length 3
  TOP w0.5: U1301.206 C1401.2 R1407.1
90OHM_DM: length 2.5
  TOP w0.11: L0702.3 99.75,37.83 99.67,37.76 D0704.1 J0701.36
90OHM_DP: length 2.5
  TOP w0.11: J0701.38 D0702.1 100.47,37.62 100.35,37.75 L0702.4
90OHM_USB2_HOST2_DM: length 3.6
  TOP w0.11: U1301.292 60.55,32.58 60.15,32.18 60.15,31.97 61.19,30.94 61.54,30.94 61.77,30.7 R0698.1
90OHM_USB2_HOST2_DM_A: length 41.5
  TOP w0.11: R0601.2 61.38,28.98 61.38,28.82 61.66,28.54 64.16,28.54 65.09,29.46 73.69,29.46 74.65,28.5 74.65,26.27 78.91,22.01 84.29,22.01 85.86,20.44 85.86,20.04 86.02,19.88 86.34,19.88 86.45,19.77 D0608.1 86.45,18.88 86.16,18.59 86.16,17.94 87.73,16.36 87.73,14.59 88.07,14.25 89.3,14.25 89.62,14.57 89.62,15.21 89.51,15.32 88.72,15.32
90OHM_USB2_HOST2_DM_B: length 49.6
  TOP w0.11: R0698.2 v1(62.67,29.35) ; v1(99.33,38.73) 99.7,38.73 L0702.1
  BOTTOM w0.11: v1(99.33,38.73) 99.5,38.9 100.06,38.9 100.17,38.79 100.17,37.97 99.72,37.52 97.25,37.52 95.94,36.21 95.94,32.12 95.08,31.26 84.19,31.26 82.24,29.31 64.71,29.31 63.97,28.57 61.8,28.57 61.69,28.68 61.69,29.24 61.8,29.35 v1(62.67,29.35)
90OHM_USB2_HOST2_DP: length 3.4
  TOP w0.11: U1301.289 60.8,31.02 R0699.1
90OHM_USB2_HOST2_DP_A: length 41.8
  TOP w0.11: R0608.2 60.8,29.1 61.58,28.32 64.25,28.32 65.17,29.25 73.6,29.25 74.44,28.41 74.44,26.18 78.83,21.8 84.2,21.8 85.65,20.35 D0603.1 85.65,18.85 85.95,18.55 85.95,17.85 87.53,16.27 87.53,14.5 87.98,14.04 89.39,14.04 89.83,14.48 89.83,15.21 89.94,15.32 90.72,15.32
90OHM_USB2_HOST2_DP_B: length 49.8
  TOP w0.11: L0702.2 100.4,38.73 v1(100.78,38.73) ; R0699.2 60.27,29.9 60.27,28.62 v1(60.33,28.57)
  BOTTOM w0.11: v1(100.78,38.73) 100.38,38.33 100.38,37.88 99.81,37.31 97.34,37.31 96.15,36.12 96.15,32.03 95.17,31.05 84.28,31.05 82.33,29.1 64.8,29.1 64.06,28.36 61.72,28.36 61.5,28.57 v1(60.33,28.57)
90OHM_USB2_HOST3_DM: length 33.9
  TOP w0.11: U1301.297 63.75,32.73 63.15,32.12 63.15,31.48 64.39,30.23 74.04,30.23 75.47,28.8 75.47,26.62 79.3,22.8 86.46,22.8 88.5,20.76 88.5,20.52 88.95,20.07 R0611.1
90OHM_USB2_HOST3_DM_A: length 14
  TOP w0.11: R0611.2 88.92,18.8 D0606.1 88.92,17.25 89.14,17.04 91.22,17.04 92.22,16.02 92.22,12.23 91.36,11.37 90.11,11.37 89.62,11.86 89.62,12.6 89.51,12.71 88.72,12.71
90OHM_USB2_HOST3_DP: length 34.2
  TOP w0.11: R0616.1 88.1,20.1 88.29,20.29 88.29,20.68 86.38,22.59 79.21,22.59 75.27,26.54 75.27,28.71 73.95,30.02 64.3,30.02 62.94,31.39 62.94,32.02 62.83,32.12 62.38,32.12 62.15,32.36 U1301.295
90OHM_USB2_HOST3_DP_A: length 13.8
  TOP w0.11: 90.72,12.71 89.94,12.71 89.83,12.6 89.83,11.95 90.2,11.57 91.28,11.57 92.02,12.31 92.02,15.94 91.13,16.82 89.05,16.82 88.72,17.16 88.72,17.34 88.53,17.52 88.23,17.52 88.12,17.63 D0601.1 88.12,18.8 R0616.2
90OHM_USB3_HOST1_DM: length 127.1
  TOP w0.11: U1301.83 36.27,69.75 36.27,70.3 36.71,70.73 36.71,71.94 37.34,72.56 37.34,74.09 36.02,75.4 32.77,75.4 30.61,77.56 11.61,77.56 11.02,76.96 11.02,26.56 17.01,20.57 19.51,20.57 24.2,15.88 36.41,15.88 42.26,21.73 45.68,21.73 46.16,21.24 46.16,20.89 45.73,20.45 R0621.1
90OHM_USB3_HOST1_DM_A: length 10.5
  TOP w0.11: v1(45.77,17.73) D0357.1 45.77,19.15 R0621.2
  INNER LAYER 3 w0.09: J0301.11 49.84,14.21 50.94,15.31 50.94,16.21 50.08,17.07 46.65,17.07 46,17.73 v1(45.77,17.73)
90OHM_USB3_HOST1_DP: length 128.8
  TOP w0.11: R0619.1 46.58,20.45 46.38,20.65 46.38,21.32 45.77,21.93 42.17,21.93 36.33,16.09 24.29,16.09 19.6,20.77 17.1,20.77 11.22,26.65 11.22,76.87 11.7,77.35 30.52,77.35 32.69,75.19 35.94,75.19 37.12,74 37.12,72.65 36.5,72.03 36.5,70.82 35.98,70.3 35.98,68.7 37.1,67.58 U1301.79
90OHM_USB3_HOST1_DP_A: length 8.9
  TOP w0.11: v1(46.58,17.73) D0356.1 R0619.2
  INNER LAYER 3 w0.09: J0301.12 51.03,15.13 51.14,15.23 51.14,16.29 50.16,17.27 46.73,17.27 46.58,17.43 v1(46.58,17.73)
90OHM_USB3_HOST1_SSRXN: length 115.2
  TOP w0.11: R0341.2 51.3,21.5 50.81,21.99 50.81,22.31 50.36,22.76 50.36,22.9 50.13,23.14 49.99,23.14 49.62,23.51 41.56,23.51 35.7,17.65 25.03,17.65 20.2,22.48 17.67,22.48 12.79,27.36 12.79,70.91 15.94,74.06 22.81,74.06 28.66,68.22 31.81,68.22 32.14,68.54 33.15,68.54 33.35,68.74 U1301.92
90OHM_USB3_HOST1_SSRXN_A1: length 8.4
  TOP w0.11: R0341.1 51.3,19.93 51.02,19.65 D0359.1 D0359.10 51.02,18.12 50.86,17.96 50.86,17.19 51.32,16.73 54.46,16.73 54.65,16.54 54.65,16.33 J0301.14
90OHM_USB3_HOST1_SSRXP: length 118.9
  TOP w0.11: R0340.2 50.45,21.52 50.6,21.68 50.6,22.23 49.9,22.93 49.53,23.3 41.65,23.3 35.79,17.44 24.94,17.44 20.11,22.27 17.59,22.27 12.57,27.27 12.57,71 15.85,74.28 22.9,74.28 28.75,68.42 31.73,68.42 32.05,68.75 32.33,68.75 32.7,69.12 32.7,69.99 32.93,70.22 33.8,70.22 34.05,69.97 34.05,68.38 34.15,68.28 U1301.89
90OHM_USB3_HOST1_SSRXP_A1: length 5.2
  TOP w0.11: R0340.1 50.45,19.9 50.52,19.82 D0359.2 D0359.9 50.52,18.1 50.65,17.98 50.65,17.1 J0301.15
90OHM_USB3_HOST1_SSTXN: length 123.3
  TOP w0.11: U1301.88 34.95,72.08 35.54,72.67 35.54,73.86 34.99,74.42 30.93,74.42 28.8,76.55 13.45,76.55 12,75.1 12,27.05 17.42,21.62 19.9,21.62 24.66,16.86 36.01,16.86 41.88,22.73 48.73,22.73 48.96,22.5 48.96,22.14 49.6,21.5 C0361.2
90OHM_USB3_HOST1_SSTXN_A1: length 8.9
  TOP w0.11: J0301.17 48.03,14.91 47.88,14.75 47.58,14.75 46.95,15.38 46.95,16.32 47.6,16.98 48.87,16.98 49.36,17.46 49.36,17.98 49.52,18.15 D0359.7 D0359.4 49.52,19.77 49.6,19.85 C0361.1
90OHM_USB3_HOST1_SSTXP: length 125.8
  TOP w0.11: C0360.2 48.75,22.41 48.64,22.52 41.96,22.52 36.09,16.65 24.57,16.65 19.81,21.41 17.34,21.41 11.79,26.96 11.79,75.19 13.36,76.76 28.89,76.76 31.02,74.62 35.08,74.62 35.75,73.95 35.75,72.58 35.16,71.99 35.16,70.64 35.55,70.25 35.55,68.4 35.75,68.2 U1301.84
90OHM_USB3_HOST1_SSTXP_A1: length 6.7
  TOP w0.11: J0301.18 46.04,15.71 47.51,17.18 48.78,17.18 49.15,17.55 49.15,18 49.02,18.12 D0359.6 D0359.5 49.02,19.65 48.75,19.93 C0360.1
90OHM_USB3_OTG0_DM: length 148
  TOP w0.11: J0302.2 35.63,5.38 35.83,5.58 35.83,6.03 35.55,6.3 D0302.1 35.55,6.93 35.56,6.94 35.56,7.39 TP0301.1 36.33,8.93 40.05,8.93 42.32,6.65 57.5,6.65 60.27,9.43 60.27,15.8 56.35,19.73 56.35,21.85 52.58,25.62 40.62,25.62 34.79,19.79 25.96,19.79 21.11,24.64 18.59,24.64 14.99,28.23 14.99,51.47 15.29,51.77 15.29,68.84 16.89,70.44 20.19,70.44 23.32,67.3 24.57,67.3 25.85,66.03 U1301.113
90OHM_USB3_OTG0_DP: length 147.8
  TOP w0.11: U1301.112 24.73,66.67 24.9,66.5 24.9,66.14 24.71,65.95 23.39,65.95 23.2,66.14 23.2,67.12 20.1,70.22 16.97,70.22 15.5,68.75 15.5,51.68 15.2,51.38 15.2,28.32 18.67,24.85 21.2,24.85 26.05,20 34.7,20 40.54,25.84 52.66,25.84 56.56,21.94 56.56,19.81 60.48,15.89 60.48,9.34 57.59,6.44 42.23,6.44 39.96,8.71 37.16,8.71 36.98,8.53 TP0302.1 36.59,7.78 36.36,7.54 36.36,6.94 36.35,6.93 D0303.1 36.35,6.33 36.03,6.01 36.03,5.62 36.28,5.37 J0302.3
90OHM_USB3_OTG0_SSRX_N: length 16.4
  TOP w0.11: J0301.5 54.66,13.14 54.89,13.14 55.99,12.04 57.59,12.04 59.2,13.65 59.2,16.02 57.9,17.32 55.27,17.32 55.17,17.43 D0301.6 55.17,19.6 55.4,19.82 R0322.1
90OHM_USB3_OTG0_SSRX_P: length 18.2
  TOP w0.11: R0323.1 54.55,19.7 54.67,19.58 D0301.7 54.67,17.63 55.19,17.11 57.81,17.11 58.99,15.94 58.99,13.74 57.5,12.25 56.08,12.25 54.98,13.35 52.87,13.35 J0301.6
90OHM_USB3_OTG0_SSRXN: length 104.8
  TOP w0.11: R0322.2 55.4,21.48 55.1,21.77 55.1,22.25 52.29,25.06 40.86,25.06 35.03,19.23 25.73,19.23 20.88,24.07 18.32,24.07 14.43,27.97 14.43,51.93 14.72,52.23 14.72,69.25 17.21,71.74 19.74,71.74 23.2,68.28 23.2,67.85 23.35,67.7 25.05,67.7 25.27,67.47 U1301.110
90OHM_USB3_OTG0_SSRXP: length 102.7
  TOP w0.11: U1301.109 23.5,68.28 19.82,71.95 17.13,71.95 14.52,69.34 14.52,52.31 14.21,52.02 14.21,27.89 18.24,23.86 20.79,23.86 25.64,19.02 35.12,19.02 40.95,24.85 52.2,24.85 54.89,22.16 54.89,21.77 54.55,21.43 R0323.2
90OHM_USB3_OTG0_SSTX_N: length 27.3
  TOP w0.11: C0307.1 53.7,19.85 53.67,19.82 D0301.9 53.67,17.75 v1(53.77,17.65)
  INNER LAYER 3 w0.09: J0301.8 47.77,12.52 47.37,12.12 47.37,11.99 48,11.36 48,10.46 48.83,9.62 53.84,9.62 56.54,12.32 57.42,12.32 58.95,13.86 58.95,15.48 55.98,18.45 53.9,18.45 53.52,18.07 53.52,17.9 v1(53.77,17.65)
90OHM_USB3_OTG0_SSTX_P: length 29.3
  TOP w0.11: C0309.1 52.85,19.9 53.17,19.57 D0301.10 53.17,17.73 v1(53.1,17.65)
  INNER LAYER 3 w0.09: v1(53.1,17.65) 53.33,17.88 53.33,18.16 53.82,18.65 56.06,18.65 59.15,15.56 59.15,13.78 57.5,12.12 56.62,12.12 53.92,9.43 48.75,9.43 47.8,10.38 47.8,11.27 47.17,11.91 47.17,12.19 46.84,12.52 J0301.9
90OHM_USB3_OTG0_SSTXN: length 105.1
  TOP w0.11: C0307.2 53.7,21.43 53.35,21.77 53.35,22.27 51.34,24.29 41.19,24.29 35.35,18.45 25.4,18.45 20.57,23.27 17.97,23.27 17.3,23.95 17.3,23.95 13.65,27.6 13.65,52.38 13.95,52.68 13.95,69.72 17.14,72.92 19.69,72.92 23.3,69.3 25.07,69.3 25.3,69.08 U1301.108
90OHM_USB3_OTG0_SSTXP: length 103.3
  TOP w0.11: U1301.107 23.02,69.88 19.77,73.12 17.05,73.12 13.74,69.81 13.74,52.77 13.44,52.47 13.44,27.51 17.21,23.74 17.21,23.74 17.89,23.07 20.49,23.07 25.31,18.24 35.44,18.24 41.28,24.07 51.25,24.07 53.14,22.19 53.14,21.71 52.85,21.43 C0309.2
100OHM_EDP_TX_AUXN: length 9.8
  TOP w0.092: C0515.2 21.2,51.33 21.62,51.75 21.89,51.75 22.32,52.18 22.32,53.25 23.02,53.95 23.02,55.98 23.26,56.22 23.95,56.22 24.16,56.43 24.61,56.43 24.82,56.65 24.82,57.25 25.45,57.88 U1301.137
100OHM_EDP_TX_AUXN1: length 12.5
  TOP w0.092: C0515.1 R0505.2 19.07,51.4 v1(18.52,51.4)
  BOTTOM w0.092: 11.72,44.88 12.67,44.88 12.96,45.16 13.87,45.16 17.9,49.2 17.9,51.48 17.99,51.58 18.35,51.58 v1(18.52,51.4)
100OHM_EDP_TX_AUXP: length 7.4
  TOP w0.092: C0536.1 21.23,52.17 21.44,51.96 21.81,51.96 22.11,52.27 22.11,53.34 22.82,54.04 22.82,56.06 23.18,56.42 23.86,56.42 23.95,56.52 U1301.141
100OHM_EDP_TX_AUXP1: length 14.8
  TOP w0.092: C0536.2 R0519.2 19.07,52.1 v1(18.52,52.1)
  BOTTOM w0.092: v1(18.52,52.1) 18.21,51.79 17.91,51.79 17.69,51.57 17.69,49.29 13.78,45.38 9.32,45.38
100OHM_EDP_TX_D0N: length 9.7
  TOP w0.092: C0509.2 20.82,54.95 21.27,54.5 21.93,54.5 22.11,54.69 22.11,56.44 22.79,57.11 22.79,58.96 23.08,59.25 25.62,59.25 U1301.132
100OHM_EDP_TX_D0N1: length 13.3
  TOP w0.092: C0509.1 19.52,54.88 v1(18.98,54.88)
  BOTTOM w0.092: v1(18.98,54.88) 18.7,54.6 17.9,54.6 16.89,53.59 16.89,50.24 13.35,46.69 12.85,46.69 12.67,46.88 11.72,46.88
100OHM_EDP_TX_D0P: length 7.8
  TOP w0.092: C0534.1 20.88,54.1 21.07,54.29 22.02,54.29 22.32,54.6 22.32,56.35 23,57.02 23,58.88 23.16,59.04 23.34,59.04 23.7,58.67 U1301.136
100OHM_EDP_TX_D0P1: length 15.7
  TOP w0.092: v1(18.98,54.17) 19.52,54.17 C0534.2
  BOTTOM w0.092: 9.32,46.38 12.7,46.38 12.81,46.48 13.43,46.48 17.1,50.15 17.1,53.5 17.99,54.39 18.76,54.39 v1(18.98,54.17)
100OHM_EDP_TX_D1N: length 8.6
  TOP w0.092: U1301.127 23.3,61.08 22.96,60.74 22.96,60.16 22.09,59.29 22.09,57.54 21.2,56.65 20.98,56.65 20.8,56.83 C0531.2
100OHM_EDP_TX_D1N1: length 15.7
  TOP w0.092: v1(18.98,56.75) 19.52,56.75 C0531.1
  BOTTOM w0.092: v1(18.98,56.75) 18.73,56.51 18.01,56.51 16.19,54.69 16.19,51.36 13.31,48.48 10.76,48.48 10.65,48.38 9.32,48.38
100OHM_EDP_TX_D1P: length 8.8
  TOP w0.092: U1301.131 24.5,60.27 24.7,60.48 24.7,60.77 24.61,60.87 23.39,60.87 23.18,60.65 23.18,60.08 22.3,59.2 22.3,57.45 20.82,55.98 C0513.1
100OHM_EDP_TX_D1P1: length 15.6
  TOP w0.092: C0513.2 19.52,56.05 v1(18.98,56.05)
  BOTTOM w0.092: 11.72,47.88 10.82,47.88 10.72,47.97 10.72,48.16 10.74,48.16 10.85,48.27 13.4,48.27 16.4,51.27 16.4,54.6 18.1,56.3 18.73,56.3 v1(18.98,56.05)
100OHM_EDP_TX_D2N: length 8.5
  TOP w0.092: C0529.2 20.82,58.73 21.11,58.44 21.3,58.44 21.39,58.53 21.39,59.61 22.27,60.49 22.27,61.61 22.74,62.09 23.01,62.09 23.35,62.42 25.05,62.42 25.3,62.67 U1301.122
100OHM_EDP_TX_D2N1: length 14.3
  TOP w0.092: C0529.1 19.5,58.62 v1(18.98,58.62)
  BOTTOM w0.092: 11.72,49.88 12.58,49.88 12.74,49.71 13.37,49.71 15.29,51.64 15.29,55.79 17.69,58.19 18.41,58.19 18.5,58.28 18.5,58.53 18.59,58.62 v1(18.98,58.62)
100OHM_EDP_TX_D2P: length 6.4
  TOP w0.092: C0505.1 20.82,57.88 21.18,58.23 21.39,58.23 21.6,58.44 21.6,59.53 22.48,60.4 22.48,61.52 22.82,61.88 U1301.126
100OHM_EDP_TX_D2P1: length 16.3
  TOP w0.092: C0505.2 19.5,57.98 v1(18.98,57.98)
  BOTTOM w0.092: v1(18.98,57.98) 17.77,57.98 15.5,55.7 15.5,51.55 13.32,49.38 9.32,49.38
100OHM_EDP_TX_D3N: length 8.3
  TOP w0.092: U1301.117 22.73,64.28 21.54,63.09 21.54,60.8 21.15,60.41 21.02,60.41 20.82,60.6 C0510.2
100OHM_EDP_TX_D3N1: length 16.1
  TOP w0.092: v1(19,60.5) 19.52,60.5 C0510.1
  BOTTOM w0.092: v1(19,60.5) 18.9,60.5 14.49,56.09 14.49,52.79 13.19,51.48 10.76,51.48 10.65,51.38 9.32,51.38
100OHM_EDP_TX_D3P: length 9
  TOP w0.092: U1301.121 24.85,63.48 24.94,63.57 24.94,63.96 24.84,64.06 22.81,64.06 21.75,63 21.75,60.72 20.79,59.75 C0532.1
100OHM_EDP_TX_D3P1: length 15.8
  TOP w0.092: C0532.2 19.55,59.83 v1(19,59.83)
  BOTTOM w0.092: v1(19,59.83) 18.83,60 18.7,60 14.7,56 14.7,52.7 13.28,51.27 10.85,51.27 10.75,51.18 10.75,51.02 10.9,50.88 11.72,50.88
100OHM_HDMI_CLK_N_1: length 10.9
  TOP w0.092: R0462.2 3.08,15.97 3.2,15.85 U0408.4 3.2,14.55 4.3,13.45 8.28,13.45 8.95,12.78 8.95,12.35 8.7,12.1 J0401.12
100OHM_HDMI_CLK_P_1: length 11.2
  TOP w0.092: R0461.2 3.88,15.97 3.75,15.85 U0408.3 3.75,15.4 3.41,15.06 3.41,14.64 4.39,13.66 8.37,13.66 9.16,12.87 9.16,12.56 9.7,12.03 J0401.10
100OHM_HDMI_TX0_N_1: length 8.9
  TOP w0.092: R0460.2 6.9,15.97 7,15.88 7,14.76 7.43,14.32 9.35,14.32 10.59,13.09 10.59,12.52 10.2,12.12 J0401.9
100OHM_HDMI_TX0_P_1: length 9.1
  TOP w0.092: J0401.7 11.2,12.15 10.8,12.55 10.8,13.18 9.44,14.54 7.52,14.54 7.21,14.84 7.21,15.06 7.3,15.15 7.46,15.15 7.55,15.24 7.55,15.85 7.67,15.97 R0459.2
100OHM_HDMI_TX0N_PORT: length 101.1
  TOP w0.092: R1402.2 44.12,76.69 44.03,76.79 43.9,76.79 43.8,76.88 43.8,77.1 42.89,78.01 37.31,78.01 36.84,77.53 33.84,77.53 31.66,79.71 10.64,79.71 8.88,77.95 8.88,26 7.14,24.26 7.14,17.64 7,17.5 U0404.2 7,16.97 6.91,16.88 R0460.1
100OHM_HDMI_TX0N_PORT1: length 4.1
  TOP w0.092: R1402.1 44.12,75.1 43.96,74.94 43.96,72.64 44.05,72.55 44.37,72.55 44.55,72.73 U1301.61
100OHM_HDMI_TX0P_PORT: length 100.4
  TOP w0.092: R1401.2 43.27,76.69 43.37,76.79 43.5,76.79 43.59,76.88 43.59,77.01 42.8,77.8 37.4,77.8 36.92,77.33 33.75,77.33 31.57,79.5 10.72,79.5 9.09,77.86 9.09,25.91 7.35,24.18 7.35,17.68 7.55,17.48 U0404.1 7.55,17 7.67,16.88 R0459.1
100OHM_HDMI_TX0P_PORT1: length 4.2
  TOP w0.092: U1301.62 43.75,74.6 43.27,75.08 R1401.1
100OHM_HDMI_TX1_N_1: length 6.6
  TOP w0.092: J0401.6 11.7,12.07 11.85,12.22 11.85,14.03 10.9,14.97 10.9,15.68 10.8,15.78 10.8,15.88 10.7,15.97 R0458.2
100OHM_HDMI_TX1_P_1: length 6.9
  TOP w0.092: R0457.2 11.47,15.97 11.35,15.85 11.35,15.57 11.15,15.38 11.15,15.02 12.08,14.09 12.08,12.59 12.7,11.97 J0401.4
100OHM_HDMI_TX1N_PORT: length 100.7
  TOP w0.092: R0458.1 10.7,16.88 10.8,16.98 U0411.2 10.8,17.48 10.99,17.66 10.99,19.86 9.56,21.29 9.56,22.19 9.47,22.28 8.87,22.28 8.65,22.49 8.65,22.85 8.87,23.07 9.47,23.07 9.56,23.16 9.56,23.34 9.47,23.43 8.87,23.43 8.65,23.65 8.65,24.01 8.87,24.22 9.47,24.22 9.56,24.31 9.56,77.61 10.96,79.01 31.31,79.01 33.49,76.83 37.14,76.83 37.61,77.31 41.89,77.31 42.1,77.1 42.1,76.88 42.2,76.79 42.26,76.79 42.33,76.72 R1408.2
100OHM_HDMI_TX1N_PORT1: length 4.4
  TOP w0.092: U1301.66 42.95,72.71 42.77,72.53 42.45,72.53 42.36,72.62 42.36,74.14 41.98,74.52 41.98,74.72 42.33,75.08 R1408.1
100OHM_HDMI_TX1P_PORT: length 100.2
  TOP w0.092: R1403.2 41.48,76.72 41.54,76.79 41.8,76.79 41.9,76.88 41.9,77.01 41.8,77.1 37.7,77.1 37.23,76.62 33.4,76.62 31.23,78.8 11.05,78.8 9.78,77.53 9.78,24.23 9.56,24.01 8.95,24.01 8.86,23.92 8.86,23.74 8.95,23.64 9.56,23.64 9.78,23.43 9.78,23.07 9.56,22.86 8.95,22.86 8.86,22.76 8.86,22.58 8.95,22.49 9.56,22.49 9.78,22.27 9.78,21.38 11.2,19.95 11.2,17.65 11.35,17.5 U0411.1 11.35,16.98 11.45,16.88 R0457.1
100OHM_HDMI_TX1P_PORT1: length 4.3
  TOP w0.092: R1403.1 41.48,75.03 41.77,74.73 41.77,74.44 42.15,74.05 U1301.67
100OHM_HDMI_TX2_N_1: length 6.7
  TOP w0.092: R0466.2 14.5,15.97 14.6,15.88 14.6,14.55 13.44,13.39 13.44,12.43 13.2,12.19 J0401.3
100OHM_HDMI_TX2_P_1: length 7.2
  TOP w0.092: J0401.1 14.2,12.21 13.98,12.43 13.74,12.43 13.65,12.52 13.65,13.3 14.81,14.46 14.81,15.06 14.9,15.15 15,15.15 15.15,15.3 15.15,15.88 15.25,15.97 R0455.2
100OHM_HDMI_TX2N_PORT: length 99.2
  TOP w0.092: R0466.1 14.47,16.88 14.6,17 U0403.2 14.6,17.5 14.77,17.66 14.77,19.68 13.8,20.65 13.8,20.96 14.27,21.43 14.27,21.56 14.14,21.69 14.01,21.69 13.54,21.22 13.23,21.22 12.98,21.47 12.98,21.77 13.45,22.25 13.45,22.38 13.32,22.51 13.19,22.51 12.72,22.03 12.42,22.03 12.16,22.29 12.16,22.59 12.63,23.06 12.63,23.19 12.5,23.32 12.37,23.32 11.9,22.85 11.6,22.85 11.35,23.1 11.35,23.41 11.82,23.88 11.82,24.01 11.69,24.14 11.56,24.14 11.08,23.67 10.78,23.67 10.27,24.18 10.27,77.31 11.26,78.31 31.02,78.31 33.19,76.14 36.47,76.14 36.67,75.93 37.46,75.93 37.78,76.25 R1406.2
100OHM_HDMI_TX2N_PORT1: length 6
  TOP w0.092: U1301.71 41.35,72.58 41.22,72.44 40.82,72.44 40.76,72.5 40.76,74.84 39.66,75.94 39.37,75.94 R1406.1
100OHM_HDMI_TX2P_PORT: length 98.9
  TOP w0.092: R1405.2 37.8,75.4 37.48,75.72 36.58,75.72 36.38,75.92 33.1,75.92 30.93,78.1 11.35,78.1 10.47,77.23 10.47,24.27 10.87,23.88 11,23.88 11.47,24.35 11.77,24.35 12.03,24.1 12.03,23.79 11.56,23.32 11.56,23.19 11.69,23.06 11.82,23.06 12.29,23.53 12.59,23.53 12.84,23.28 12.84,22.98 12.37,22.5 12.37,22.37 12.5,22.24 12.63,22.24 13.11,22.72 13.41,22.72 13.66,22.46 13.66,22.16 13.19,21.69 13.19,21.56 13.32,21.43 13.45,21.43 13.92,21.9 14.23,21.9 14.48,21.64 14.48,21.34 14.01,20.87 14.01,20.74 14.97,19.77 14.97,17.68 15.15,17.5 U0403.1 15.15,17 15.28,16.88 R0455.1
100OHM_HDMI_TX2P_PORT1: length 5.4
  TOP w0.092: R1405.1 39.38,75.72 39.58,75.72 40.55,74.75 U1301.72
100OHM_HDMI_TXCLKN_PORT: length 105.6
  TOP w0.092: R0462.1 3.1,16.88 3.2,16.98 U0408.2 3.2,17.45 3.39,17.64 3.39,21.66 8.16,26.44 8.16,78.24 10.33,80.41 31.97,80.41 34.15,78.22 36.52,78.22 37.01,78.71 44.02,78.71 45.55,77.18 45.55,76.94 45.92,76.56 R1404.2
100OHM_HDMI_TXCLKN_PORT1: length 4.3
  TOP w0.092: U1301.56 46.15,72.67 45.98,72.5 45.65,72.5 45.56,72.59 45.56,74.71 45.92,75.08 R1404.1
100OHM_HDMI_TXCLKP_PORT: length 105
  TOP w0.092: R0461.1 3.85,16.88 3.75,16.98 U0408.1 3.75,17.48 3.6,17.62 3.6,17.9 3.72,18.02 3.72,18.3 3.6,18.41 3.6,18.69 3.72,18.81 3.72,19.08 3.6,19.2 3.6,21.58 8.38,26.35 8.38,78.15 10.42,80.2 31.88,80.2 34.06,78.02 36.61,78.02 37.1,78.5 43.93,78.5 45.34,77.09 45.34,76.94 45.08,76.67 R1409.2
100OHM_HDMI_TXCLKP_PORT1: length 4.1
  TOP w0.092: U1301.57 45.35,74.78 45.08,75.05 R1409.1
100OHM_LAN0_MDI0N_A: length 9.9
  BOTTOM w0.092: U0901.11 108.88,34.68 109.21,35.01 109.21,35.17 108.99,35.39 107.47,35.39 107.22,35.63 107.22,35.98 107.08,36.12 D0906.2 D0906.9 107.08,37.7 107.22,37.84 107.22,38.36 106.89,38.69 106.89,39.66 106.17,40.38 106.17,40.8 106.08,40.9 U0902.2
100OHM_LAN0_MDI0P_A: length 10
  BOTTOM w0.092: U0901.12 109.87,34.8 109.08,35.6 107.55,35.6 107.44,35.72 107.44,35.98 107.58,36.12 D0906.1 D0906.10 107.58,37.7 107.43,37.84 107.43,38.45 107.1,38.77 107.1,39.75 106.38,40.47 106.38,40.8 106.47,40.9 U0902.1
100OHM_LAN0_MDI1N_A: length 8.3
  BOTTOM w0.092: U0902.5 104.88,40.9 104.97,40.8 104.97,39.88 105.72,39.12 105.72,37.73 105.58,37.58 D0906.6 D0906.5 105.58,36.12 105.77,35.94 105.77,35.76 106.29,35.24 106.29,35.09 105.91,34.71 U0901.8
100OHM_LAN0_MDI1P_A: length 8.3
  BOTTOM w0.092: 105.28,41.17 105.28,40.9 105.18,40.8 105.18,39.97 105.94,39.21 105.94,37.72 106.08,37.58 D0906.7 D0906.4 106.08,36.12 105.97,36.02 105.97,35.85 106.5,35.33 106.5,35.13 106.92,34.7 106.92,33.73 U0901.9
100OHM_LAN0_MDI2N_A: length 8.1
  BOTTOM w0.092: U0902.7 104.08,40.9 104.17,40.8 104.17,39.17 103.45,38.45 103.45,37.77 103.33,37.65 D0904.9 D0904.2 103.33,36.15 103.47,36.01 103.47,35.24 102.92,34.7 102.92,33.73 U0901.5
100OHM_LAN0_MDI2P_A: length 8.1
  BOTTOM w0.092: U0902.6 104.47,40.9 104.38,40.8 104.38,39.08 103.67,38.38 103.67,37.77 103.83,37.62 D0904.10 D0904.1 103.83,36.17 103.68,36.03 103.68,35.75 103.8,35.64 103.8,35.36 103.68,35.24 103.68,34.95 103.92,34.7 103.92,33.72 U0901.6
100OHM_LAN0_MDI3N_A: length 9.6
  BOTTOM w0.092: U0901.2 99.92,33.76 99.92,34.7 100.31,35.09 100.31,35.34 100.61,35.63 101.87,35.63 101.97,35.73 101.97,36 101.83,36.15 D0904.5 D0904.6 101.83,37.62 101.97,37.77 101.97,38.81 102.97,39.82 102.97,40.78 102.88,40.88 U0902.10
100OHM_LAN0_MDI3P_A: length 9.6
  BOTTOM w0.092: 103.28,41.17 103.28,40.88 103.18,40.78 103.18,39.73 102.17,38.73 102.17,37.8 102.33,37.65 D0904.7 D0904.4 102.33,36.15 102.18,36 102.18,35.64 101.96,35.42 100.7,35.42 100.53,35.25 100.53,35.1 100.92,34.7 100.92,33.74 U0901.3
100OHM_LAN0_RJ45_D0M_A: length 18.3
  BOTTOM w0.092: J0901.2 111.06,9.55 111.4,9.55 111.72,9.87 111.72,11.05 108.59,14.19 108.59,19.34 109.72,20.46 109.72,22.87 109.62,22.96 109.27,22.96 108.92,23.3 108.92,24.25 U0901.14
100OHM_LAN0_RJ45_D0P_A: length 18.3
  BOTTOM w0.092: U0901.13 109.92,24.23 109.92,23.16 110.04,23.04 110.04,22.76 109.92,22.64 109.92,22.37 110.04,22.25 110.04,21.97 109.92,21.86 109.92,21.58 110.04,21.46 110.04,21.19 109.92,21.07 109.92,20.38 108.8,19.25 108.8,14.27 111.94,11.14 111.94,10.57 112.05,10.46 112.05,10.18 111.94,10.06 111.94,9.79 111.52,9.37 J0901.1
100OHM_LAN0_RJ45_D1M_A: length 22.9
  BOTTOM w0.092: U0901.17 105.92,24.27 105.92,23.3 106.32,22.9 106.32,20.13 107.49,18.96 107.49,12.59 109.39,10.69 109.39,9.56 108.38,8.55 108.38,7.85 107.85,7.33 107.03,7.33 106.42,7.93 J0901.6
100OHM_LAN0_RJ45_D1P_A: length 22.8
  BOTTOM w0.092: J0901.3 109.48,6.34 109.65,6.17 110.23,6.17 110.45,6.39 110.45,8.72 109.6,9.57 109.6,10.78 107.7,12.68 107.7,19.05 106.53,20.22 106.53,22.9 106.92,23.3 106.92,24.27 U0901.16
100OHM_LAN0_RJ45_D2M_A: length 18.3
  BOTTOM w0.092: U0901.20 102.92,24.27 102.92,23.28 103.23,22.98 103.45,22.98 103.64,22.79 103.64,21.21 103.84,21.02 103.84,20.85 104.03,20.66 104.2,20.66 104.39,20.46 104.39,20.29 104.59,20.1 104.75,20.1 104.95,19.9 104.95,19.74 105.14,19.54 105.31,19.54 106.53,18.33 106.53,11.91 107.34,11.1 107.34,9.45 107.44,9.35 J0901.5
